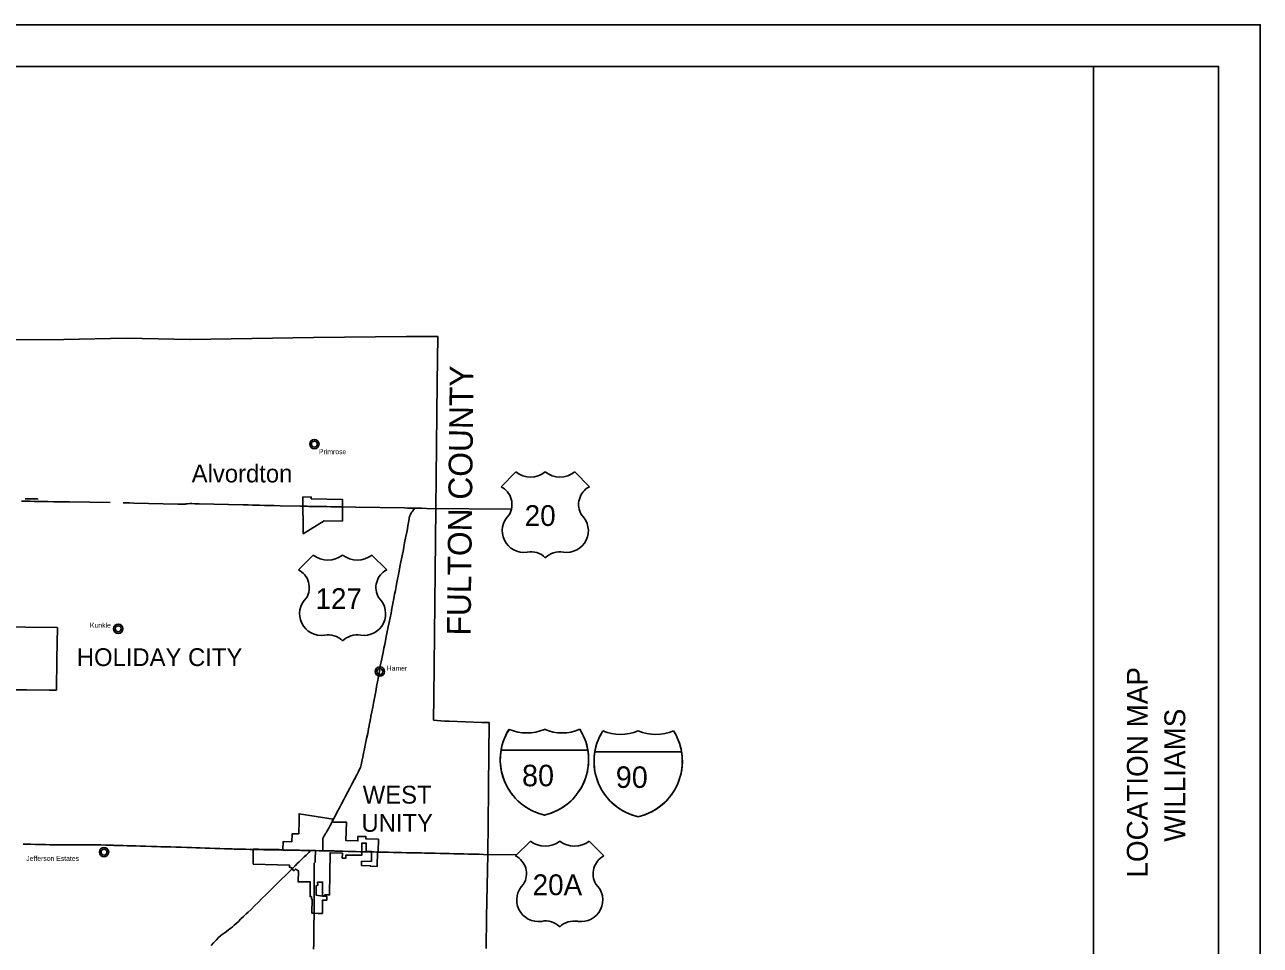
# Model space of a CAD drawing. Extents: x -66 to 795, y 0 to 440.
# Drawn here: x 383.6 to 680, y 219 to 440 of the extents above; entities that cross this region are included whole.
import ezdxf

# ---------------------------------------------------------------- set-up
doc = ezdxf.new("R2010")
doc.units = 0
for name, color, linetype in [('Default', 7, 'Continuous'), ('DV_X_Corp_Line', 7, 'Continuous'), ('GM_X_Adjacent_County_Text', 7, 'Continuous'), ('GM_X_Corporation_Text', 7, 'Continuous'), ('GM_X_County', 7, 'Continuous'), ('GM_X_State_Route', 7, 'Continuous'), ('GM_X_US_Route', 7, 'Continuous'), ('PV_P_Text', 7, 'Continuous'), ('SH_Border', 7, 'Continuous'), ('SH_Cut_Line', 7, 'Continuous'), ('SH_Data', 7, 'Continuous')]:
    doc.layers.add(name, color=color, linetype=linetype)

msp = doc.modelspace()

# ---------------------------------------------------------------- linework, layer by layer
at = {"layer": 'DV_X_Corp_Line'}
for points in [[(452.32, 326.16), (452.33, 326.61), (450.36, 326.64), (450.42, 317.83), (455.44, 320.92), (459.82, 320.85)], [(459.82, 320.85), (459.85, 326), (452.32, 326.16)], [(376.33, 295.52), (383.84, 295.4), (391.44, 295.29), (391.32, 287.8), (391.22, 280.27), (389.47, 280.3), (384.04, 280.33), (375.91, 280.38)]]:
    msp.add_lwpolyline(points, dxfattribs=at)
msp.add_lwpolyline([(438.39, 238.49), (438.42, 242.09), (439.68, 242.07), (440.26, 242.06), (440.67, 242.06), (441.61, 242.04), (442.09, 242.03), (443.38, 242.01), (444.63, 241.99), (445.51, 241.97), (445.58, 243.94), (447.69, 243.9), (447.74, 245.76), (449.34, 245.75), (449.41, 248.99), (449.44, 250.59), (457.63, 249.29), (457.33, 248.72), (457.78, 248.6), (460.83, 248.55), (460.65, 244.18), (463.53, 244.07), (463.55, 245.16), (465.46, 245.12), (465.45, 244.55), (468.46, 244.47), (468.38, 241.5), (468.23, 241.51), (468.17, 237.97), (466.52, 237.99), (466.52, 238.13), (464.4, 238.19), (464.41, 238.59), (464.41, 238.85), (464.42, 239.22), (466.77, 239.18), (466.77, 239.94), (466.8, 241.54), (465.75, 241.57), (465.5, 241.57), (465.54, 243.55), (464.49, 243.56), (464.46, 241.59), (464.44, 240.65), (460.66, 240.67), (460.65, 239.96), (459.79, 239.98), (459.82, 241.18), (456.85, 241.25), (456.75, 231.12), (455.59, 231.13), (455.58, 230.96), (455.35, 230.87), (455.06, 230.89), (455.06, 234.22), (453.87, 234.22), (453.88, 233.43), (453.55, 233.31), (453.53, 231.03), (455.06, 230.83), (456.05, 230.78), (456.05, 229.88), (455.05, 229.89), (455.04, 228.74), (455.01, 226.69), (454.02, 226.7), (453.02, 226.72), (452.5, 226.74), (452.52, 230.15), (452.37, 230.16), (452.36, 230.71), (452.07, 230.72), (452.09, 234.27), (449.17, 234.25), (449.25, 236.92), (448.56, 237.32), (448.14, 236.93), (447.74, 237.39), (447.69, 237.44), (447.83, 237.58), (447.11, 237.79), (447.12, 238.27)], close=True, dxfattribs=at)
for centre, radius in [((453.08, 339.34), 1.12), ((453.08, 339.34), 0.71), ((406.04, 295.01), 1.12), ((406.04, 295.01), 0.71), ((468.8, 284.72), 1.12), ((468.8, 284.72), 0.71), ((402.63, 241.4), 1.12), ((402.63, 241.4), 0.71)]:
    msp.add_circle(centre, radius, dxfattribs=at)
at = {"layer": 'GM_X_County'}
msp.add_lwpolyline([(494.26, 218.28), (494.39, 225.79), (494.67, 240.85), (494.84, 256.19), (494.85, 256.83), (494.85, 257.23), (495.01, 272.51), (493.26, 272.5), (485.43, 272.8), (484.29, 272.85), (481.69, 273.07), (481.75, 278.62), (481.92, 293.61), (482.08, 308.69), (482.25, 323.91), (482.33, 331.2), (482.42, 339), (482.57, 354.1), (482.69, 365.19), (475.15, 365.12), (460.31, 364.96), (452.91, 364.93), (438.06, 364.69), (423.32, 364.45), (423.21, 364.45), (407.97, 364.76), (392.99, 364.44), (377.99, 364.37)], dxfattribs=at)
at = {"layer": 'GM_X_State_Route'}
for points in [[(453.06, 238.41), (453.07, 238.73), (453.09, 238.8), (453.13, 238.86), (453.29, 238.98), (453.3, 238.99), (453.29, 239.07), (453.3, 239.28), (453.3, 239.47), (453.31, 240.26), (453.33, 241.12), (453.36, 241.75)], [(453.04, 234.22), (453.04, 235.35), (453.04, 236.24), (453.06, 237.14), (453.05, 237.87), (453.06, 238.4), (453.06, 238.41), (453.06, 238.41)], [(453.04, 226.74), (453.04, 226.74), (453.04, 227.87), (453.03, 229.25), (453.03, 230.64), (453.04, 231.79), (453.04, 233.1), (453.04, 234.14), (453.04, 234.22), (453.04, 234.22)], [(452.9, 218.12), (452.92, 219.3), (452.94, 220.44), (452.95, 221.7), (452.98, 223.16), (452.99, 224.45), (453.01, 225.6), (453.02, 225.83)], [(453.02, 225.83), (453.04, 226.59), (453.04, 226.67), (453.04, 226.74)]]:
    msp.add_lwpolyline(points, dxfattribs=at)
at = {"layer": 'GM_X_US_Route'}
for points in [[(383.71, 326.19), (384.16, 326.19), (384.92, 326.18), (385.77, 326.17), (386.62, 326.16), (386.77, 326.15), (386.77, 326.15)], [(382.84, 325.64), (383.86, 325.62), (384.9, 325.6), (385.95, 325.59), (386.85, 325.57), (387.9, 325.55), (389.11, 325.53), (390.56, 325.5), (392.05, 325.49), (393.16, 325.46), (394.34, 325.46), (404.14, 325.29)], [(407.19, 325.25), (407.65, 325.23), (408.72, 325.21), (409.8, 325.18), (420.33, 324.93), (421.06, 324.92), (421.61, 324.92), (421.88, 324.93), (422.08, 324.95), (422.3, 324.98), (422.67, 325), (423.24, 325.04), (423.68, 325.04), (424.4, 325.02), (425.43, 325), (435.99, 324.76), (437.19, 324.73), (438.22, 324.7), (439.34, 324.67), (439.96, 324.65), (441.1, 324.63), (443.46, 324.57), (444.85, 324.55), (449.74, 324.44), (449.96, 324.43)], [(449.96, 324.43), (450.27, 324.43)], [(450.27, 324.43), (451.03, 324.41)], [(451.03, 324.41), (451.28, 324.4), (451.77, 324.39), (452.26, 324.39), (453.23, 324.37), (454.2, 324.36), (455.12, 324.33)], [(455.12, 324.33), (455.13, 324.33), (456.09, 324.32), (457.11, 324.31), (458.04, 324.3), (459.01, 324.29), (459.94, 324.28)], [(459.94, 324.28), (462.95, 324.23)], [(462.95, 324.23), (474.7, 324.04), (475.43, 323.95), (476.35, 323.95), (477.15, 323.95)], [(466.51, 273.21), (466.52, 273.22), (466.67, 274.02), (466.87, 275.04), (467.08, 276.15), (467.27, 277.15), (467.42, 277.94), (467.57, 278.73), (467.72, 279.51), (467.89, 280.4), (468.03, 281.17), (468.11, 281.57), (468.23, 282.26), (468.5, 283.53), (468.65, 284.32), (468.75, 284.86), (468.77, 285.18), (468.81, 285.58), (468.87, 285.92), (468.98, 286.45), (469.11, 287.03), (469.28, 287.79), (469.44, 288.59), (469.59, 289.34), (469.79, 290.34), (469.97, 291.22), (470.14, 292.09), (470.34, 293.13), (470.5, 293.84), (470.51, 293.9), (470.65, 294.67), (470.82, 295.49), (471.01, 296.52), (471.25, 297.66), (471.48, 298.77), (471.7, 299.89), (471.85, 300.66), (472, 301.48), (472.16, 302.31), (472.34, 303.3), (472.52, 304.21), (472.71, 305.17), (472.89, 306.23), (473.17, 307.67), (473.4, 308.87), (473.59, 309.84), (473.83, 311.09), (474.12, 312.55), (474.43, 314.07), (474.74, 315.65), (475.03, 317.17), (475.24, 318.16), (475.41, 319.03), (475.52, 319.7), (475.65, 320.5), (475.79, 321.43), (475.85, 321.72), (475.95, 322.04), (476.08, 322.39), (476.22, 322.63), (476.33, 322.81), (476.53, 323.05), (476.87, 323.54), (477.15, 323.95)], [(477.15, 323.95), (477.89, 323.94), (478.84, 323.92), (479.97, 323.91), (500.36, 323.7)], [(457.6, 249.17), (457.61, 249.2), (458.13, 250.18), (458.59, 251.06), (459.1, 252.03), (459.62, 253.02), (460.16, 254.03), (460.59, 254.86), (461.1, 255.83), (461.59, 256.73), (462.09, 257.67), (462.64, 258.73), (463.26, 259.93), (463.69, 260.78), (463.95, 261.31), (464.14, 261.72), (464.24, 262.01), (464.33, 262.32), (464.43, 262.75), (464.59, 263.55), (464.73, 264.2), (464.9, 265.05), (465.14, 266.21), (465.38, 267.44), (465.63, 268.63), (465.88, 269.86), (466.1, 271), (466.24, 271.73), (466.27, 271.87), (466.46, 272.92), (466.47, 272.96), (466.51, 273.21)], [(457.33, 248.64), (457.33, 248.64), (457.6, 249.17), (457.6, 249.17)], [(455.29, 244.97), (455.29, 244.97), (455.47, 245.3), (455.62, 245.56), (455.77, 245.83), (455.88, 246.01)], [(455.88, 246.01), (455.88, 246.02), (456.14, 246.47), (456.52, 247.15), (456.88, 247.8), (457.26, 248.51), (457.33, 248.64)], [(383.23, 243.32), (384.19, 243.3), (385.06, 243.27), (386.17, 243.24), (387.18, 243.22), (387.97, 243.2), (388.48, 243.19), (388.57, 243.19), (389.51, 243.18), (390.51, 243.17), (391.27, 243.16), (392.25, 243.15), (393.19, 243.13), (394.17, 243.13), (395.11, 243.12), (395.91, 243.12), (396.65, 243.12), (397.61, 243.13), (398.63, 243.13), (399.64, 243.13), (400.56, 243.15), (401.2, 243.13), (401.83, 243.13), (403.03, 243.08), (404.05, 243.05), (404.81, 243.03)], [(455.09, 241.71), (455.1, 242.63), (455.1, 242.68), (455.1, 243.58), (455.1, 243.61), (455.11, 244.2), (455.11, 244.54), (455.11, 244.56), (455.11, 244.61), (455.15, 244.7), (455.29, 244.97)], [(404.81, 243.03), (404.81, 243.03), (405.07, 243.02), (406.28, 243), (407.25, 242.97), (408.16, 242.94), (409.1, 242.92), (410.24, 242.88), (411.37, 242.84), (412.55, 242.82), (414.02, 242.77), (415.27, 242.73)], [(415.27, 242.73), (416.22, 242.7), (417.44, 242.66), (418.45, 242.64), (418.45, 242.64)], [(418.45, 242.64), (418.62, 242.63), (419.82, 242.6), (421.13, 242.55), (422.46, 242.51), (423.58, 242.48), (424.62, 242.44), (425.71, 242.41), (426.86, 242.37), (428.05, 242.33), (429.31, 242.29), (430.44, 242.26), (431.53, 242.22), (432.45, 242.19), (433.38, 242.15), (433.84, 242.14), (434.41, 242.12), (435.48, 242.1), (436.53, 242.07), (437.58, 242.06), (438.42, 242.04), (438.75, 242.03)], [(438.75, 242.03), (438.81, 242.03), (439.9, 241.99), (440.99, 241.98), (441.89, 241.97), (442.96, 241.95), (443.93, 241.93), (444.96, 241.91), (445.51, 241.9), (445.54, 241.9), (445.57, 241.9)], [(445.57, 241.9), (445.98, 241.9), (446.4, 241.89), (446.72, 241.88), (447.27, 241.87), (447.52, 241.87), (447.66, 241.87), (447.69, 241.87)], [(447.69, 241.87), (448.32, 241.86), (448.61, 241.85), (448.92, 241.84), (449.51, 241.83), (450.04, 241.82), (450.45, 241.81), (450.88, 241.8), (451.16, 241.8), (451.73, 241.78), (452.19, 241.76)], [(448.03, 237.66), (448.46, 238.09), (448.97, 238.63), (449.41, 239.04), (449.48, 239.1), (449.77, 239.38), (449.8, 239.4), (450.2, 239.82), (450.65, 240.26), (451.09, 240.69), (451.74, 241.31), (452.19, 241.76)], [(452.19, 241.76), (452.62, 241.75), (452.63, 241.75)], [(452.63, 241.75), (452.63, 241.75), (452.72, 241.75), (453.36, 241.75)], [(453.36, 241.75), (454.26, 241.73), (454.28, 241.73), (455.09, 241.71)], [(455.09, 241.71), (456.03, 241.7), (456.07, 241.7), (456.93, 241.69), (457.04, 241.69), (457.04, 241.69)], [(457.04, 241.69), (457.77, 241.67), (458.03, 241.66), (458.57, 241.64), (458.97, 241.63), (459.13, 241.62)], [(459.13, 241.62), (459.14, 241.62), (459.98, 241.6), (461.18, 241.58), (462.02, 241.55), (463.1, 241.52), (464.16, 241.5), (464.52, 241.49)], [(464.52, 241.49), (465.2, 241.47), (465.27, 241.47)], [(465.27, 241.47), (465.28, 241.47), (466.38, 241.45), (467.07, 241.44)], [(467.07, 241.44), (467.4, 241.43), (467.96, 241.42)], [(467.96, 241.42), (468.26, 241.41)], [(468.26, 241.41), (468.26, 241.41), (468.44, 241.4), (469.63, 241.38), (470.88, 241.36), (472, 241.33), (472.95, 241.32), (474.05, 241.28), (475.18, 241.26), (476.29, 241.24), (477.53, 241.21), (478.8, 241.19), (479.51, 241.17), (479.75, 241.17), (481.01, 241.15), (482.06, 241.13), (483.29, 241.09), (484.39, 241.07), (485.42, 241.04), (486.55, 241.02), (487.76, 240.98), (488.95, 240.95), (490.02, 240.92), (490.78, 240.91), (491.74, 240.89), (492.62, 240.88), (493.65, 240.86), (501.56, 240.77)], [(428.31, 218.96), (428.91, 219.6), (429.58, 220.33), (430.1, 220.89), (430.53, 221.32), (430.71, 221.47), (431, 221.66), (431.44, 221.97), (432.02, 222.38), (432.51, 222.75), (433.03, 223.15), (433.43, 223.46), (433.53, 223.54), (433.86, 223.83), (434.21, 224.16), (434.85, 224.77), (435.48, 225.37), (436.1, 225.96), (436.75, 226.57), (437.24, 227.01), (437.9, 227.66), (438.8, 228.55), (439.59, 229.33), (440.59, 230.31), (441.44, 231.14), (441.74, 231.44), (442.23, 231.92), (443.2, 232.87), (444.04, 233.71), (444.66, 234.32), (445.38, 235.04), (446.15, 235.79), (446.87, 236.51), (447.6, 237.24), (447.87, 237.51), (447.92, 237.56)], [(447.92, 237.56), (447.98, 237.62), (448.03, 237.66)]]:
    msp.add_lwpolyline(points, dxfattribs=at)
at = {"layer": 'PV_P_Text'}
for p, q in [((501.44, 332.64), (497.89, 329.1)), ((501.44, 332.64), (497.89, 329.1)), ((519.07, 329.1), (515.53, 332.64)), ((519.07, 329.1), (515.53, 332.64)), ((452.82, 312.7), (449.27, 309.16)), ((470.45, 309.16), (466.91, 312.7)), ((497.88, 265.88), (518.68, 265.88)), ((518.68, 265.88), (497.88, 265.88)), ((518.68, 265.88), (497.88, 265.88)), ((520.37, 265.49), (541.17, 265.49)), ((541.17, 265.49), (520.37, 265.49)), ((541.17, 265.49), (520.37, 265.49)), ((504.91, 244.02), (501.37, 240.48)), ((522.55, 240.48), (519, 244.02))]:
    msp.add_line(p, q, dxfattribs=at)
for centre, radius, start, end in [((504.96, 337.12), 5.7, 231.813, 308.187), ((504.96, 337.12), 5.7, 231.813, 308.187), ((512.01, 337.12), 5.7, 231.813, 308.187), ((512.01, 337.12), 5.7, 231.813, 308.187), ((495.67, 324.82), 4.82, 329.1175, 62.6108), ((495.67, 324.82), 4.82, 329.1175, 62.6108), ((521.29, 324.82), 4.82, 117.3892, 210.8825), ((521.29, 324.82), 4.82, 117.3892, 210.8825), ((503.36, 318.54), 5.2, 133.0046, 278.7282), ((503.36, 318.54), 5.2, 133.0046, 278.7282), ((513.61, 318.54), 5.2, 261.2718, 46.9954), ((513.61, 318.54), 5.2, 261.2718, 46.9954), ((456.34, 317.18), 5.7, 231.813, 308.187), ((463.39, 317.18), 5.7, 231.813, 308.187), ((505.1, 308.85), 4.65, 43.4177, 101.8742), ((505.1, 308.85), 4.65, 43.4177, 101.8742), ((511.96, 308.54), 4.94, 79.9613, 134.7468), ((511.96, 308.54), 4.94, 79.9613, 134.7468), ((447.05, 304.88), 4.82, 329.1175, 62.6108), ((472.67, 304.88), 4.82, 117.3892, 210.8825), ((454.74, 298.6), 5.2, 133.0046, 278.7282), ((464.99, 298.6), 5.2, 261.2718, 46.9954), ((456.48, 288.91), 4.65, 43.4177, 101.8742), ((463.34, 288.6), 4.94, 79.9613, 134.7468), ((511.36, 263.59), 13.67, 147.8216, 256.9941), ((510.5, 263.83), 12.79, 146.654, 170.759), ((504.04, 280.91), 10.91, 247.0848, 292.9105), ((504.04, 280.91), 10.91, 247.0848, 292.9105), ((505.21, 263.59), 13.67, 283.0065, 32.1787), ((512.53, 280.92), 10.91, 247.0916, 292.9084), ((512.53, 280.92), 10.91, 247.0916, 292.9084), ((505.21, 263.59), 13.67, 9.6475, 32.179), ((533.84, 263.2), 13.67, 147.8216, 256.9941), ((532.99, 263.44), 12.79, 146.654, 170.759), ((526.52, 280.53), 10.91, 247.0848, 292.9105), ((526.52, 280.53), 10.91, 247.0848, 292.9105), ((527.69, 263.2), 13.67, 283.0065, 32.1787), ((535.01, 280.53), 10.91, 247.0916, 292.9084), ((535.01, 280.53), 10.91, 247.0916, 292.9084), ((527.69, 263.2), 13.67, 9.6475, 32.179), ((511.36, 263.59), 13.67, 170.3514, 256.9967), ((505.23, 263.58), 13.64, 282.7667, 9.6898), ((533.84, 263.2), 13.67, 170.3514, 256.9967), ((527.72, 263.2), 13.64, 282.7667, 9.6898), ((508.44, 248.5), 5.7, 231.813, 308.187), ((515.48, 248.5), 5.7, 231.813, 308.187), ((499.15, 236.2), 4.82, 329.1175, 62.6108), ((524.77, 236.2), 4.82, 117.3892, 210.8825), ((506.83, 229.92), 5.2, 133.0046, 278.7282), ((517.08, 229.92), 5.2, 261.2718, 46.9954), ((508.58, 220.23), 4.65, 43.4177, 101.8742), ((515.43, 219.92), 4.94, 79.9613, 134.7468)]:
    msp.add_arc(centre, radius, start, end, dxfattribs=at)
at = {"layer": 'SH_Border'}
msp.add_line((640, 10), (640, 430), dxfattribs=at)
msp.add_lwpolyline([(30, 430), (670, 430), (670, 10), (30, 10)], close=True, dxfattribs=at)
at = {"layer": 'SH_Cut_Line'}
msp.add_lwpolyline([(0, 0), (680, 0), (680, 440), (0, 440)], close=True, dxfattribs=at)

# ---------------------------------------------------------------- texts
at = {"layer": 'Default'}
msp.add_text('Alvordton', height=4.275, dxfattribs=at).set_placement((423.66, 330.14))
at = {"layer": 'DV_X_Corp_Line'}
for s, height, p in [('Primrose', 1.188, (454.19, 336.91)), ('Kunkle', 1.188, (399.25, 295.25)), ('Hamer', 1.188, (470.44, 284.93)), ('Jefferson Estates', 1.1875, (383.97, 239.29))]:
    msp.add_text(s, height=height, rotation=0, dxfattribs=at).set_placement(p)
at = {"layer": 'GM_X_Adjacent_County_Text'}
msp.add_text('FULTON COUNTY', height=5.7, rotation=89.3585, dxfattribs=at).set_placement((490.56, 293.36))
at = {"layer": 'GM_X_Corporation_Text'}
for s, p in [('HOLIDAY CITY', (396.1, 286.05)), ('WEST', (464.69, 253.04)), ('UNITY', (464.38, 246.28))]:
    msp.add_text(s, height=4.275, rotation=0, dxfattribs=at).set_placement(p)
at = {"layer": 'PV_P_Text'}
for s, height, p in [('20', 4.987, (503.55, 319.68)), ('127', 4.987, (453.36, 299.74)), ('80', 5.162, (502.9, 257.2)), ('90', 5.162, (525.39, 256.81)), ('20A', 4.987, (505.46, 231.06))]:
    msp.add_text(s, height=height, dxfattribs=at).set_placement(p)
at = {"layer": 'SH_Data'}
for s, p in [('LOCATION MAP', (653, 235.29)), ('WILLIAMS', (662, 243.88))]:
    msp.add_text(s, height=5, rotation=90, dxfattribs=at).set_placement(p)

doc.saveas('drawing.dxf')
